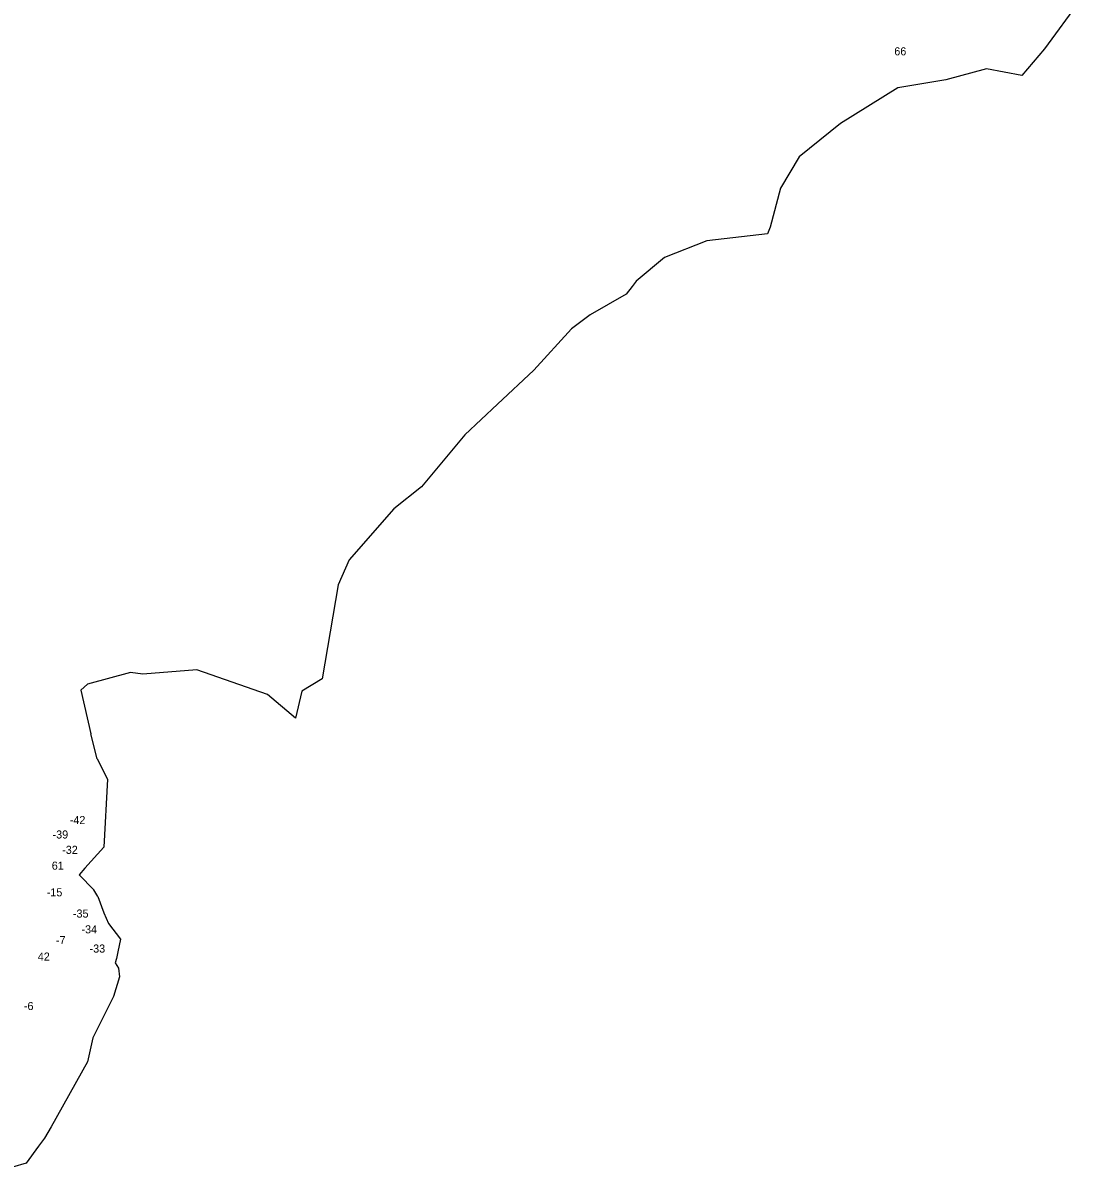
# Model space of a CAD drawing. Extents: x -788458 to -784980, y -976879 to -973650.
# Drawn here: x -786723 to -785414, y -976517 to -975096 of the extents above; entities that cross this region are included whole.
import ezdxf

# ---------------------------------------------------------------- set-up
doc = ezdxf.new("R2010")
doc.units = 0
for name, color, linetype in [('Vrstva 13', 7, 'Continuous'), ('Vrstva 24', 7, 'Continuous'), ('Vrstva 63', 7, 'Continuous')]:
    doc.layers.add(name, color=color, linetype=linetype)

msp = doc.modelspace()

# ---------------------------------------------------------------- linework, layer by layer
at = {"layer": 'Vrstva 13'}
for p, q in [((-785414, -975067.1), (-785458, -975127.8)), ((-785458, -975127.8), (-785486.2, -975160.6)), ((-785529.9, -975152.4), (-785580.1, -975166.3)), ((-785486.2, -975160.6), (-785529.9, -975152.4)), ((-785639.7, -975176), (-785710.6, -975220.4)), ((-785580.1, -975166.3), (-785639.7, -975176)), ((-785710.6, -975220.4), (-785761.6, -975261.5)), ((-785761.6, -975261.5), (-785785, -975300.2)), ((-785785, -975300.2), (-785797.5, -975348.5)), ((-785797.5, -975348.5), (-785801, -975356.9)), ((-785801, -975356.9), (-785876, -975365.3)), ((-785876, -975365.3), (-785928.6, -975386)), ((-785928.6, -975386), (-785963.8, -975415.4)), ((-785963.8, -975415.4), (-785968.5, -975422.1)), ((-785975.9, -975431.4), (-786020.7, -975457.3)), ((-785968.5, -975422.1), (-785975.9, -975431.4)), ((-786020.7, -975457.3), (-786043.8, -975474.4)), ((-786043.8, -975474.4), (-786090.4, -975525.8)), ((-786090.4, -975525.8), (-786135.4, -975567.8)), ((-786135.4, -975567.8), (-786175.6, -975605.6)), ((-786175.6, -975605.6), (-786229.3, -975670.2)), ((-786229.3, -975670.2), (-786263.7, -975697.3)), ((-786263.7, -975697.3), (-786318.9, -975760.6)), ((-786318.9, -975760.6), (-786332.4, -975791.5)), ((-786332.4, -975791.5), (-786352.5, -975907.6)), ((-786589.9, -975899.9), (-786642.8, -975914.4)), ((-786574.3, -975901.9), (-786589.9, -975899.9)), ((-786507.4, -975896.7), (-786574.3, -975901.9)), ((-786420.2, -975927), (-786507.4, -975896.7)), ((-786642.8, -975914.4), (-786651, -975922)), ((-786352.5, -975907.6), (-786377.5, -975923)), ((-786651, -975922), (-786639, -975975.8)), ((-786385.4, -975956.3), (-786420.2, -975927)), ((-786377.5, -975923), (-786385.4, -975956.3)), ((-786631.1, -976006.9), (-786639, -975975.8)), ((-786631.1, -976006.9), (-786618.1, -976031.9)), ((-786618.1, -976031.9), (-786622.8, -976116)), ((-786622.8, -976116), (-786646.3, -976142.3)), ((-786646.3, -976142.3), (-786653.4, -976150.3)), ((-786653.4, -976150.3), (-786635.3, -976169)), ((-786630.3, -976177.1), (-786635.3, -976169)), ((-786630.3, -976177.1), (-786622.8, -976197.6)), ((-786622.8, -976197.6), (-786616.8, -976210.7)), ((-786616.8, -976210.7), (-786602.2, -976230.2)), ((-786602.2, -976230.2), (-786605.3, -976245.9)), ((-786607, -976254.2), (-786608.7, -976259.3)), ((-786608.7, -976259.3), (-786604.6, -976266.2)), ((-786605.3, -976245.9), (-786607, -976254.2)), ((-786604.6, -976266.2), (-786603.5, -976276.6)), ((-786603.5, -976276.6), (-786610.7, -976301.2)), ((-786610.7, -976301.2), (-786636.2, -976352.3)), ((-786636.2, -976352.3), (-786642.8, -976382.1)), ((-786642.8, -976382.1), (-786688, -976462.4)), ((-786688, -976462.4), (-786696, -976476.7)), ((-786703.4, -976486.6), (-786718.7, -976507.3)), ((-786696, -976476.7), (-786703.4, -976486.6)), ((-786718.7, -976507.3), (-786753, -976517.2))]:
    msp.add_line(p, q, dxfattribs=at)

# ---------------------------------------------------------------- texts
at = {"layer": 'Vrstva 24'}
for s, p in [('66', (-785644, -975135.8)), ('-42', (-786664.9, -976087.6)), ('-39', (-786686.2, -976105.5)), ('-32', (-786674.3, -976124.5)), ('61', (-786687.2, -976144.1)), ('-15', (-786693.4, -976177.1)), ('-35', (-786661, -976203.4)), ('-34', (-786650.4, -976222.9)), ('-7', (-786682, -976236.3)), ('-33', (-786640.4, -976246.7)), ('-6', (-786721.7, -976317.9))]:
    msp.add_text(s, height=10, dxfattribs=at).set_placement(p)
at = {"layer": 'Vrstva 63'}
msp.add_text('42', height=10, dxfattribs=at).set_placement((-786704.5, -976256.7))

doc.saveas('drawing.dxf')
